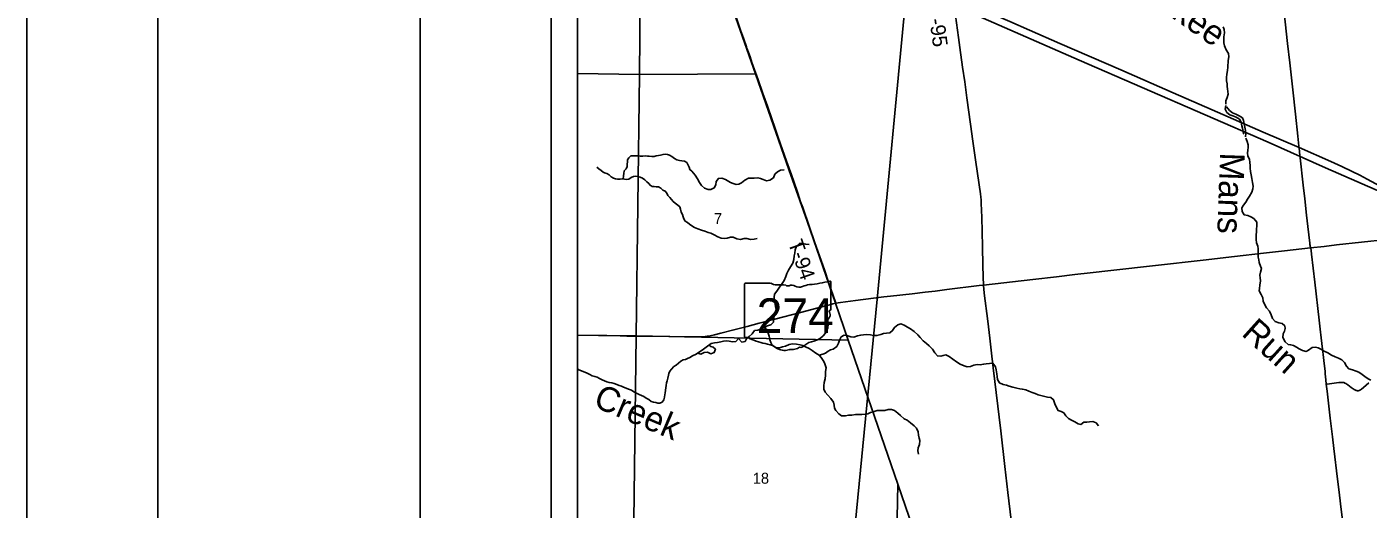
# Model space of a CAD drawing. Extents: x 0 to 34, y -5.4 to 22.
# Drawn here: x 0 to 5.12, y 16.49 to 18.33 of the extents above; entities that cross this region are included whole.
import ezdxf

# ---------------------------------------------------------------- set-up
doc = ezdxf.new("R2010")
doc.units = 0
for name, color, linetype in [('Default', 7, 'Continuous'), ('GM_X_Minor_River', 7, 'Continuous'), ('GM_X_Minor_River_Text', 7, 'Continuous'), ('GM_X_Rail_Line', 7, 'Continuous'), ('GM_X_Section', 7, 'Continuous'), ('GM_X_Section_Text', 7, 'Continuous'), ('GM_X_State_Location', 7, 'Continuous'), ('GM_X_State_Route', 7, 'Continuous'), ('GM_X_State_Shield', 7, 'Continuous'), ('GM_X_Township_Road', 7, 'Continuous'), ('GM_X_Township_Road_Text', 7, 'Continuous'), ('GM_X_US_Route', 7, 'Continuous'), ('SH_Border', 7, 'Continuous'), ('SH_Cut_Line', 7, 'Continuous'), ('SH_Data', 7, 'Continuous')]:
    doc.layers.add(name, color=color, linetype=linetype)

msp = doc.modelspace()

# ---------------------------------------------------------------- linework, layer by layer
at = {"layer": 'Default'}
for points in [[(2.1, 19.1639), (2.1, 18.1542), (2.3371, 18.1505), (2.3463, 19.1601)], [(2.1, 18.1542), (2.1, 17.1559), (2.3239, 17.1531), (2.3371, 18.1505)], [(2.1, 17.1559), (2.1, 16.1508), (2.3117, 16.1481), (2.3239, 17.1531)]]:
    msp.add_lwpolyline(points, close=True, dxfattribs=at)
at = {"layer": 'GM_X_Minor_River'}
for points in [[(4.5637, 18.333), (4.5673, 18.3223), (4.5686, 18.3094), (4.5661, 18.2951), (4.5659, 18.2814), (4.5665, 18.2719), (4.5682, 18.2609), (4.5747, 18.2445), (4.5836, 18.2306), (4.5849, 18.2181), (4.582, 18.2049), (4.5816, 18.1783), (4.5795, 18.1662), (4.5781, 18.1522), (4.576, 18.1393), (4.5758, 18.1264), (4.5783, 18.115), (4.5792, 18.1051), (4.5795, 18.0957), (4.5812, 18.0861), (4.5822, 18.0759), (4.5789, 18.0634), (4.5742, 18.0506), (4.5732, 18.0373)], [(4.5743, 18.032), (4.5714, 18.0184), (4.5772, 18.0065), (4.5892, 17.9965), (4.6009, 17.9936), (4.6133, 17.9877), (4.6264, 17.9799), (4.6326, 17.9684), (4.6351, 17.9555), (4.6368, 17.9456), (4.6392, 17.9322), (4.6428, 17.9227)], [(4.5768, 18.027), (4.588, 18.0136), (4.5995, 18.005), (4.6123, 17.9991), (4.6251, 17.9936), (4.6371, 17.985), (4.6407, 17.9755), (4.6431, 17.9625), (4.646, 17.9503), (4.6488, 17.9378), (4.6505, 17.9256), (4.6491, 17.9131)], [(4.6494, 17.9078), (4.6549, 17.8956), (4.6592, 17.8826), (4.6594, 17.8727), (4.6581, 17.8621), (4.6568, 17.8511), (4.6582, 17.8409), (4.6636, 17.8271), (4.6649, 17.8165), (4.6662, 17.8028), (4.6665, 17.7933), (4.6678, 17.7811), (4.6698, 17.7674), (4.6726, 17.7537), (4.675, 17.7385), (4.6774, 17.7244), (4.6773, 17.7142), (4.6733, 17.7017), (4.6643, 17.6871), (4.6569, 17.6747), (4.6503, 17.6642), (4.6407, 17.6518), (4.6345, 17.642), (4.6365, 17.6283), (4.6439, 17.6153), (4.6578, 17.6132), (4.6695, 17.608), (4.6807, 17.601), (4.6918, 17.5872), (4.6923, 17.572), (4.6907, 17.5621), (4.6901, 17.5527), (4.6895, 17.5367), (4.6889, 17.5219), (4.6902, 17.5086), (4.6953, 17.496), (4.697, 17.4861), (4.6968, 17.4759), (4.697, 17.4656), (4.6976, 17.4539), (4.699, 17.444), (4.701, 17.4329), (4.7065, 17.4199), (4.7094, 17.4104), (4.7058, 17.3968), (4.7029, 17.3847), (4.705, 17.3748), (4.706, 17.363), (4.7031, 17.3471), (4.7017, 17.3346), (4.7008, 17.3248), (4.7085, 17.3113), (4.7148, 17.2983), (4.7157, 17.2866), (4.7219, 17.2724), (4.7289, 17.2601), (4.7404, 17.2478), (4.747, 17.234), (4.7521, 17.2203), (4.7625, 17.2087), (4.7757, 17.2039), (4.7885, 17.2011), (4.7985, 17.1918), (4.7999, 17.1819), (4.7978, 17.1717), (4.7924, 17.1615), (4.791, 17.1471), (4.8006, 17.1314), (4.8114, 17.121), (4.8212, 17.1189), (4.8318, 17.1172), (4.8438, 17.1109), (4.8535, 17.1043), (4.8655, 17.098), (4.8798, 17.0944), (4.8894, 17.0991), (4.9024, 17.1088), (4.916, 17.1101), (4.9259, 17.108), (4.936, 17.1033), (4.9487, 17.0955), (4.963, 17.0884), (4.9772, 17.0798), (4.9911, 17.0735), (5.0035, 17.0684), (5.0159, 17.0625), (5.0267, 17.0516), (5.0337, 17.0379), (5.043, 17.0278), (5.0569, 17.0234), (5.0705, 17.0194), (5.081, 17.0147), (5.0933, 17.0057), (5.1034, 16.998), (5.1165, 16.9894), (5.1267, 16.9843)], [(2.2745, 17.7517), (2.2762, 17.7646), (2.2767, 17.7733), (2.2792, 17.7832), (2.2865, 17.791), (2.2897, 17.8004), (2.2906, 17.8088), (2.2907, 17.8175), (2.2916, 17.8254), (2.2963, 17.8329), (2.304, 17.8404), (2.3127, 17.841), (2.321, 17.8409), (2.3313, 17.8399), (2.34, 17.839), (2.3494, 17.8388), (2.3589, 17.8402), (2.3676, 17.8397), (2.3741, 17.8396), (2.3843, 17.8382), (2.3933, 17.8381), (2.401, 17.8406), (2.4093, 17.842), (2.4177, 17.8437), (2.4272, 17.8462), (2.4367, 17.8464), (2.4435, 17.8456), (2.4518, 17.8431), (2.46, 17.8384), (2.4709, 17.8299), (2.4799, 17.8248), (2.4893, 17.8231), (2.4987, 17.8211), (2.5086, 17.8198), (2.5176, 17.8147), (2.5231, 17.8055), (2.5264, 17.7974), (2.5289, 17.7883), (2.5367, 17.7821), (2.5427, 17.7748), (2.5497, 17.7668)], [(2.5467, 17.5665), (2.5373, 17.573), (2.5284, 17.58), (2.5201, 17.5866), (2.5111, 17.5917), (2.506, 17.5998), (2.5038, 17.6078), (2.5006, 17.6169), (2.4966, 17.6257), (2.493, 17.6364), (2.4908, 17.6455), (2.483, 17.6529), (2.4725, 17.6599), (2.4658, 17.6661), (2.4591, 17.6738), (2.4532, 17.6819), (2.4457, 17.6892), (2.4413, 17.6976), (2.4354, 17.7061), (2.4264, 17.7097), (2.4182, 17.7166), (2.4099, 17.7217), (2.4009, 17.7226), (2.3929, 17.7235), (2.3853, 17.724), (2.3775, 17.728), (2.3727, 17.7349), (2.3652, 17.7418), (2.3578, 17.7495), (2.3484, 17.755), (2.339, 17.7586), (2.3311, 17.7618), (2.3235, 17.763), (2.3144, 17.7617), (2.3056, 17.7573), (2.296, 17.7514), (2.2884, 17.7496), (2.2797, 17.7509), (2.2714, 17.7522), (2.2635, 17.7512), (2.254, 17.7513), (2.2453, 17.753), (2.2374, 17.7558), (2.2291, 17.7605), (2.2213, 17.7675), (2.2131, 17.7729), (2.204, 17.7754), (2.198, 17.7781), (2.1905, 17.7847), (2.1823, 17.7909), (2.1745, 17.7979)], [(2.5497, 17.7668), (2.5589, 17.753), (2.5659, 17.7389), (2.5737, 17.727), (2.5856, 17.7177), (2.5984, 17.7121), (2.6086, 17.7116), (2.622, 17.7182), (2.6278, 17.7295), (2.6299, 17.7423), (2.6384, 17.7543), (2.6517, 17.7556), (2.6649, 17.7501), (2.6844, 17.7391), (2.6949, 17.7348), (2.7054, 17.7312), (2.7157, 17.7325), (2.7267, 17.7376), (2.7394, 17.7473), (2.7531, 17.7554), (2.7648, 17.7548), (2.7751, 17.755), (2.7891, 17.7567), (2.7989, 17.7546), (2.8087, 17.7503), (2.8211, 17.7455), (2.8347, 17.7476), (2.8485, 17.7572), (2.8533, 17.77), (2.8633, 17.7793), (2.8755, 17.7856), (2.8884, 17.7865)], [(2.5467, 17.5665), (2.5592, 17.5621), (2.5735, 17.5569), (2.5867, 17.5537), (2.5995, 17.5485), (2.6093, 17.5457), (2.6221, 17.5386), (2.6356, 17.5316), (2.6483, 17.526), (2.6623, 17.525), (2.6718, 17.5268), (2.6844, 17.5296), (2.6946, 17.5302), (2.7089, 17.5243), (2.7228, 17.521), (2.7358, 17.5253), (2.746, 17.5255), (2.7603, 17.5215), (2.7739, 17.5231), (2.7861, 17.5256)], [(2.8139, 17.1842), (2.8242, 17.1916), (2.8375, 17.1963), (2.8483, 17.2064), (2.8488, 17.2159), (2.8509, 17.2291), (2.8595, 17.2442), (2.8581, 17.2537), (2.8564, 17.2647), (2.8551, 17.2746), (2.8526, 17.2883), (2.8506, 17.3013), (2.8519, 17.3123), (2.8604, 17.3246), (2.8716, 17.3389), (2.8782, 17.3494), (2.8895, 17.3652), (2.895, 17.3799), (2.8986, 17.3916), (2.9056, 17.4044), (2.9134, 17.4175), (2.9215, 17.4307), (2.9252, 17.445), (2.9277, 17.4586), (2.9297, 17.4685), (2.9311, 17.4821), (2.9366, 17.4957), (2.947, 17.5065), (2.9595, 17.5059), (2.9715, 17.5031), (2.9844, 17.5025)], [(2.5395, 17.0776), (2.5538, 17.0831), (2.5664, 17.0924), (2.5764, 17.099), (2.586, 17.1068), (2.5967, 17.1142), (2.6105, 17.1239), (2.6238, 17.1275), (2.634, 17.1284), (2.6469, 17.1309), (2.6571, 17.133), (2.6674, 17.1343), (2.6787, 17.133), (2.6919, 17.1308), (2.7048, 17.1321), (2.7141, 17.1438), (2.7275, 17.1299), (2.74, 17.1319), (2.7458, 17.1417), (2.7554, 17.1506), (2.7673, 17.1607), (2.7762, 17.1735), (2.7888, 17.1751), (2.801, 17.181), (2.8116, 17.1858), (2.8229, 17.178), (2.8315, 17.152), (2.8347, 17.139), (2.838, 17.1284), (2.8431, 17.1184), (2.857, 17.1098), (2.8709, 17.1084), (2.8831, 17.1113), (2.8934, 17.1145), (2.9075, 17.1203), (2.9208, 17.1228), (2.9366, 17.1217), (2.9502, 17.1192), (2.9604, 17.1168), (2.9702, 17.1121), (2.9841, 17.1057), (2.996, 17.0983), (3.0099, 17.0871), (3.023, 17.08), (3.0359, 17.084), (3.0466, 17.088), (3.0562, 17.095), (3.0657, 17.0998), (3.0763, 17.1026), (3.0898, 17.1127), (3.0964, 17.1251), (3.1, 17.1368), (3.1059, 17.1496), (3.1177, 17.1566), (3.1324, 17.1533), (3.1426, 17.1497), (3.1547, 17.1484), (3.1691, 17.1531), (3.1809, 17.1567), (3.1915, 17.1576), (3.2044, 17.1582), (3.2188, 17.1575), (3.2297, 17.1555), (3.2429, 17.1549), (3.2578, 17.1592), (3.2673, 17.1624), (3.2787, 17.1634), (3.2915, 17.165), (3.3023, 17.1736), (3.3097, 17.186), (3.3219, 17.196), (3.3337, 17.2), (3.3465, 17.1949), (3.36, 17.1867), (3.3705, 17.1804), (3.3843, 17.1699), (3.3985, 17.1571), (3.4074, 17.1467), (3.4193, 17.1348), (3.4324, 17.1239), (3.4425, 17.1154), (3.4544, 17.1034), (3.4633, 17.0888), (3.4733, 17.0773), (3.4865, 17.0759), (3.496, 17.0792), (3.5059, 17.0809), (3.5183, 17.0746), (3.5321, 17.0645), (3.546, 17.054), (3.5598, 17.0458), (3.5752, 17.0387), (3.5865, 17.0355), (3.6002, 17.0371), (3.612, 17.0423), (3.6253, 17.0439), (3.637, 17.043), (3.6495, 17.045), (3.659, 17.0468), (3.6855, 17.0494), (3.6955, 17.0359)], [(2.5596, 17.0874), (2.5716, 17.0843), (2.5838, 17.0898), (2.5971, 17.0915), (2.6098, 17.0855), (2.622, 17.0903), (2.6264, 17.1027), (2.6183, 17.1108), (2.6093, 17.1129), (2.6023, 17.1182)], [(2.4422, 16.9826), (2.4447, 16.9917), (2.4475, 17.0034), (2.4495, 17.0094), (2.4534, 17.0192), (2.4589, 17.0271), (2.4681, 17.0361), (2.4765, 17.042), (2.4858, 17.0498), (2.4946, 17.0565), (2.5038, 17.0616), (2.5121, 17.0638), (2.5205, 17.067), (2.5285, 17.0707), (2.5395, 17.0776)], [(3.0229, 17.0801), (3.0301, 17.0715), (3.0378, 17.0596), (3.0433, 17.0501), (3.0487, 17.0317), (3.047, 17.0181), (3.046, 17.0033), (3.045, 16.9897), (3.0421, 16.9757), (3.0397, 16.9628), (3.0398, 16.9506), (3.045, 16.9388), (3.0554, 16.9272), (3.0673, 16.9149), (3.0765, 16.9003), (3.0797, 16.8892), (3.0803, 16.8778), (3.0858, 16.8682), (3.097, 16.8559), (3.1071, 16.8489), (3.1218, 16.8482), (3.1351, 16.851), (3.1469, 16.8516), (3.1613, 16.8529), (3.1741, 16.8534), (3.1847, 16.8536), (3.198, 16.8549), (3.2075, 16.8566), (3.2185, 16.8606), (3.2288, 16.8639), (3.2437, 16.8693), (3.2592, 16.8687), (3.2728, 16.8688), (3.2853, 16.8724), (3.2986, 16.8726), (3.3095, 16.869), (3.3222, 16.8585), (3.333, 16.8503), (3.3472, 16.8376), (3.3577, 16.8313), (3.3708, 16.822), (3.3842, 16.8104), (3.3939, 16.8018), (3.4001, 16.7873), (3.4014, 16.7751), (3.4039, 16.7637), (3.4064, 16.7542), (3.4054, 16.7394), (3.3999, 16.7262), (3.3993, 16.7148), (3.4014, 16.7022)], [(2.1, 17.0282), (2.1054, 17.0245), (2.116, 17.0202), (2.1242, 17.0162), (2.1348, 17.0122), (2.1472, 17.006), (2.1569, 17.0008), (2.1663, 16.9984), (2.175, 16.9956), (2.1844, 16.9913), (2.1942, 16.9862), (2.2039, 16.9814), (2.2126, 16.9779), (2.2217, 16.9758), (2.2311, 16.9745), (2.2402, 16.9721), (2.2511, 16.9681), (2.2597, 16.9641), (2.2684, 16.961), (2.2763, 16.9582), (2.2861, 16.9542), (2.2951, 16.9499), (2.3064, 16.9459), (2.3154, 16.9404), (2.3282, 16.9341), (2.3364, 16.9302), (2.3443, 16.9258), (2.353, 16.9219), (2.3623, 16.916), (2.3721, 16.9102), (2.3822, 16.9028), (2.3908, 16.9), (2.3988, 16.8987), (2.4071, 16.8967), (2.415, 16.8965), (2.4234, 16.9009), (2.4297, 16.9099), (2.4321, 16.9201), (2.4341, 16.9292), (2.435, 16.9353), (2.4367, 16.9466), (2.4376, 16.9557), (2.4389, 16.9641), (2.4402, 16.9743), (2.4422, 16.9826)], [(3.6955, 17.0359), (3.698, 17.0237), (3.7, 17.0089), (3.701, 16.9986), (3.7027, 16.9868), (3.7108, 16.9741), (3.7243, 16.9686), (3.7364, 16.965), (3.7466, 16.9621), (3.7616, 16.9573), (3.7763, 16.954), (3.7873, 16.952), (3.7975, 16.9499), (3.8103, 16.9474), (3.8227, 16.9422), (3.8355, 16.9375), (3.846, 16.9335), (3.858, 16.9283), (3.8682, 16.9259), (3.8833, 16.9222), (3.8935, 16.9202), (3.9063, 16.918), (3.9168, 16.9099), (3.9218, 16.8939), (3.9265, 16.8824), (3.9335, 16.869), (3.9456, 16.8646), (3.9553, 16.8599), (3.9631, 16.848), (3.9731, 16.8387), (3.9848, 16.8324), (3.9971, 16.8254), (4.0099, 16.8176), (4.0212, 16.8151), (4.0316, 16.8237), (4.044, 16.8238), (4.0535, 16.8252), (4.0668, 16.8272), (4.0785, 16.8221), (4.0885, 16.8102)]]:
    msp.add_lwpolyline(points, dxfattribs=at)
at = {"layer": 'GM_X_Rail_Line'}
msp.add_lwpolyline([(2.1, 20.2033), (2.1, 14.1), (2.9527, 14.1), (2.9641, 14.2324), (3.0059, 14.7462), (3.0382, 15.1455), (3.0967, 15.7517), (3.13, 16.1326), (3.2432, 17.2942), (3.3599, 18.5136), (3.3607, 18.5226), (3.3669, 18.5872), (3.3865, 18.7781), (3.4297, 19.2264), (3.4301, 19.2311), (3.4303, 19.2337), (3.46, 19.8188), (3.4778, 20.1697), (3.2417, 20.1756), (2.1537, 20.2026)], close=True, dxfattribs=at)
for points in [[(8.9, 15.5944), (8.9, 19.2127), (8.5201, 19.1691), (7.2315, 19.0156), (6.9054, 18.9823), (6.6792, 18.9603), (6.4496, 18.9373), (6.0045, 18.8908), (5.7334, 18.8597), (5.7313, 18.8595), (5.378, 18.814), (5.096, 18.7806), (5.0255, 18.7742), (4.7505, 18.7432), (3.5131, 18.6037), (3.3669, 18.5872), (3.3607, 18.5226), (3.3599, 18.5136), (3.2432, 17.2942), (3.13, 16.1326)], [(2.1, 19.046), (2.5086, 18.8639), (2.5191, 18.86), (3.2213, 18.5539), (4.0144, 18.2052), (4.7357, 17.8926), (4.9545, 17.7944), (5.8917, 17.3857), (5.944, 17.3605), (5.9893, 17.3246), (6.0173, 17.2941), (6.0405, 17.2593), (6.0551, 17.2305), (6.1298, 17.0307)]]:
    msp.add_lwpolyline(points, dxfattribs=at)
at = {"layer": 'GM_X_Section'}
for points in [[(2.4277, 19.1584), (2.7791, 18.153), (2.3371, 18.1505), (2.3463, 19.1601)], [(2.3371, 18.1505), (2.7791, 18.153), (2.9068, 17.789), (2.9768, 17.5914), (3.0847, 17.2789), (3.1329, 17.1374), (2.3239, 17.1531)], [(2.3239, 17.1531), (3.1329, 17.1374), (3.323, 16.5877), (3.3134, 16.1326), (2.3117, 16.1481)], [(3.3134, 16.1326), (3.323, 16.5877), (3.4807, 16.1279)]]:
    msp.add_lwpolyline(points, close=True, dxfattribs=at)
at = {"layer": 'GM_X_State_Route'}
for points in [[(3.2697, 17.3019), (3.2947, 17.3049), (3.3774, 17.3144), (3.4262, 17.3201), (3.4644, 17.3247), (3.51, 17.3304), (3.6322, 17.3452), (3.6491, 17.3472), (3.8378, 17.369), (3.9279, 17.3794), (3.9971, 17.3871), (4.0557, 17.394), (4.1353, 17.4032), (4.3052, 17.4223), (4.4873, 17.4428), (4.6071, 17.4564), (4.7171, 17.4686), (4.7969, 17.4777), (4.8972, 17.489), (4.9487, 17.4949), (4.9955, 17.5005), (5.1865, 17.5218)], [(2.1, 17.1562), (2.1808, 17.1546), (2.2636, 17.1533), (2.2887, 17.1529), (2.3755, 17.1523), (2.453, 17.1513), (2.5081, 17.1503), (2.5645, 17.1498), (2.583, 17.1505), (2.5878, 17.151), (2.5924, 17.1515), (2.597, 17.1521), (2.6063, 17.1535), (2.6232, 17.1572), (2.6473, 17.1633), (2.6973, 17.1761), (2.7477, 17.1894), (2.7938, 17.2019), (2.8535, 17.2176), (2.9513, 17.2431), (2.9939, 17.2545), (3.047, 17.2685), (3.0633, 17.2726), (3.0747, 17.2754), (3.086, 17.2781), (3.1036, 17.2809), (3.1614, 17.2888), (3.2697, 17.3019)]]:
    msp.add_lwpolyline(points, dxfattribs=at)
at = {"layer": 'GM_X_State_Shield'}
for p, q in [((2.7376, 17.3509), (2.7376, 17.1508)), ((2.8374, 17.3544), (2.7409, 17.3544)), ((3.0672, 17.2546), (3.0672, 17.3593)), ((3.0672, 17.2546), (3.0672, 17.2546))]:
    msp.add_line(p, q, dxfattribs=at)
for centre, major_axis, start_param, end_param in [((2.7414, 17.3513), (0.00382, 0), 1.712693, 3.28349), ((2.8604, 17.3776), (0.037, 0), 4.042523, 4.731795), ((2.8727, 17.242), (0.133, 0), 1.404758, 1.657858), ((2.9029, 17.3524), (0.0107, 0), 3.836095, 5.185415), ((2.9185, 17.3292), (0.0222, 0), 0.950623, 2.079405), ((2.9944, 17.2932), (0.0703, 0), 1.699011, 2.107814), ((2.9498, 17.6272), (0.3495, 0), 4.814394, 5.042369), ((3.0636, 17.3597), (0.00367, 0), 6.141152, 7.989035), ((2.9472, 17.361), (0.0267, 0), 4.081561, 5.145723), ((3.0664, 17.2469), (0.00568, 0), 1.883978, 3.671073), ((3.0302, 17.2337), (0.0341, 0), 5.934695, 6.695948), ((3.0633, 17.2542), (0.00393, 0), 5.05454, 6.418171), ((2.9694, 17.1975), (0.0874, 0), 5.101752, 6.440018), ((3.0804, 17.2108), (0.0248, 0), 2.387724, 3.262537), ((2.7414, 17.1503), (0.00385, 0), 3.00124, 4.508301), ((2.742, 17.1708), (0.0294, 0), 4.665946, 4.897461), ((2.748, 17.1392), (0.0106, 0), 0.519207, 1.627899), ((2.8819, 17.319), (0.2524, 0), 4.195997, 4.488961), ((2.8066, 17.0609), (0.079, 0), 0.823519, 1.323587), ((2.892, 17.1382), (0.0501, 0), 4.026481, 4.996735), ((2.921, 17.0691), (0.0412, 0), 1.495662, 1.94098), ((2.9246, 17.1233), (0.0267, 0), 4.691044, 5.507374), ((2.9488, 17.1039), (0.00752, 0), 1.147584, 2.315152), ((2.9456, 17.1314), (0.0282, 0), 4.937069, 5.64225), ((3.0063, 17.0946), (0.0479, 0), 1.647645, 2.488434)]:
    msp.add_ellipse(centre, major_axis=major_axis, ratio=0.8, start_param=start_param, end_param=end_param, dxfattribs=at)
at = {"layer": 'GM_X_Township_Road'}
for points in [[(2.745, 18.2567), (2.7333, 18.289), (2.7222, 18.3204), (2.7146, 18.3424), (2.7027, 18.3775), (2.6904, 18.4139), (2.6774, 18.4512), (2.6689, 18.4762), (2.6568, 18.5108), (2.6502, 18.5295), (2.6417, 18.5536), (2.64, 18.5582)], [(3.6522, 17.3176), (3.6491, 17.3455), (3.6491, 17.3472), (3.6489, 17.3535), (3.6483, 17.3722), (3.6454, 17.4871), (3.6438, 17.5586), (3.6414, 17.64), (3.6409, 17.6528), (3.6398, 17.6729), (3.6389, 17.6831), (3.6374, 17.6958), (3.6203, 17.8158), (3.6086, 17.8963), (3.5997, 17.961), (3.5862, 18.062), (3.5776, 18.1223), (3.5694, 18.1795), (3.5593, 18.2533), (3.554, 18.2921), (3.5421, 18.3758), (3.5356, 18.4194), (3.5326, 18.4425), (3.532, 18.4478)], [(5.0306, 16.3581), (5.0117, 16.5123), (5.006, 16.5566), (5.0001, 16.6066), (4.9858, 16.7244), (4.9803, 16.7688), (4.9719, 16.8392), (4.9652, 16.8965), (4.9596, 16.9428), (4.9567, 16.9694), (4.9549, 16.986), (4.953, 17.0083), (4.9521, 17.0179), (4.951, 17.0292), (4.9489, 17.0482), (4.9448, 17.0829), (4.9425, 17.1024), (4.9376, 17.1463), (4.934, 17.1796), (4.9297, 17.2141), (4.913, 17.3585), (4.9009, 17.4647), (4.8995, 17.4787), (4.8993, 17.4806), (4.8989, 17.4829), (4.8985, 17.4847), (4.8981, 17.4861), (4.8972, 17.489), (4.8964, 17.4918), (4.8957, 17.495), (4.895, 17.4982), (4.8943, 17.5019), (4.8936, 17.5073), (4.8899, 17.5388), (4.8862, 17.5715), (4.8816, 17.6137), (4.8745, 17.6762), (4.869, 17.7281), (4.8574, 17.8325), (4.8551, 17.8551), (4.8532, 17.8719), (4.8526, 17.8772), (4.8482, 17.9159), (4.839, 17.9999), (4.8287, 18.0919), (4.8175, 18.1951), (4.8094, 18.2692), (4.796, 18.3877)], [(3.086, 17.2781), (3.0762, 17.308), (3.0584, 17.3589), (3.0423, 17.4056), (3.0254, 17.455), (3.0051, 17.5127), (2.9854, 17.5688), (2.9601, 17.6431), (2.9518, 17.6656), (2.9407, 17.698), (2.9255, 17.742), (2.9165, 17.768), (2.9028, 17.8066), (2.8907, 17.8421), (2.8659, 17.911), (2.8535, 17.9484), (2.8429, 17.9784), (2.8249, 18.0301), (2.8076, 18.0789), (2.7897, 18.13), (2.7662, 18.1972), (2.7587, 18.2184), (2.7471, 18.251), (2.745, 18.2567)], [(3.7969, 16.0976), (3.7889, 16.1601), (3.7822, 16.2212), (3.7757, 16.2774), (3.7677, 16.3453), (3.7426, 16.5563), (3.7308, 16.655), (3.7149, 16.7914), (3.6867, 17.0315), (3.679, 17.0988), (3.6735, 17.1451), (3.6652, 17.2098), (3.6524, 17.3166), (3.6522, 17.3176)], [(4.9567, 16.9694), (4.9599, 16.9698), (5.0044, 16.9751), (5.0126, 16.976), (5.0175, 16.9761), (5.021, 16.9758), (5.0238, 16.9751), (5.0264, 16.9742), (5.0282, 16.9733), (5.0315, 16.9714), (5.0349, 16.9693), (5.039, 16.9666), (5.0521, 16.957), (5.0629, 16.9494), (5.0657, 16.9474), (5.0683, 16.9461), (5.0708, 16.9451), (5.0732, 16.9445), (5.0759, 16.9442), (5.0787, 16.9443), (5.0817, 16.945), (5.0842, 16.9461), (5.0868, 16.9476), (5.0906, 16.9502), (5.0982, 16.9561), (5.1196, 16.9749)]]:
    msp.add_lwpolyline(points, dxfattribs=at)
at = {"layer": 'GM_X_US_Route'}
msp.add_lwpolyline([(3.532, 18.4478), (3.5914, 18.422), (3.7499, 18.3528), (3.8252, 18.32), (3.941, 18.2697), (4.1735, 18.1684), (4.3734, 18.0813), (4.5219, 18.0164), (4.7167, 17.9313), (4.8532, 17.8719), (4.9739, 17.8194), (5.0157, 17.8001), (5.0561, 17.7807), (5.085, 17.7662), (5.1134, 17.7513), (5.1461, 17.7339), (5.1724, 17.7191), (5.2235, 17.6893), (5.2562, 17.6694), (5.2871, 17.6497), (5.3178, 17.6291), (5.3505, 17.6064), (5.3906, 17.5783), (5.4298, 17.5482)], dxfattribs=at)
at = {"layer": 'SH_Border'}
for points in [[(0.5, 21.5), (1.5, 21.5), (1.5, 0.5), (0.5, 0.5)], [(1.5, 21.5), (33.5, 21.5), (33.5, 0.5), (1.5, 0.5)]]:
    msp.add_lwpolyline(points, close=True, dxfattribs=at)
at = {"layer": 'SH_Cut_Line'}
msp.add_lwpolyline([(0, 0), (34, 0), (34, 22), (0, 22)], close=True, dxfattribs=at)
at = {"layer": 'SH_Data'}
for p, q in [((2, 21), (2, 14)), ((2.1, 20.9), (2.1, 14.1))]:
    msp.add_line(p, q, dxfattribs=at)

# ---------------------------------------------------------------- texts
at = {"layer": 'GM_X_Minor_River_Text'}
for s, height, rotation, p in [('Cherokee', 0.09471, 325.0277, (4.0804, 18.5678)), ('Mans', 0.09474, 268.0452, (4.5517, 17.8541)), ('Run', 0.09475, 318.022, (4.6297, 17.1579)), ('Creek', 0.09474, 337.0122, (2.1564, 16.8857))]:
    msp.add_text(s, height=height, rotation=rotation, dxfattribs=at).set_placement(p)
at = {"layer": 'GM_X_Section_Text'}
for s, height, p in [('7', 0.0419, (2.621, 17.5799)), ('18', 0.04186, (2.769, 16.5894))]:
    msp.add_text(s, height=height, rotation=0, dxfattribs=at).set_placement(p)
at = {"layer": 'GM_X_State_Location'}
msp.add_text('274', height=0.000189, rotation=0, dxfattribs=at).set_placement((2.8319, 17.2238))
for s in ['s', 'r']:
    msp.add_text(s, height=0.000189, dxfattribs=at).set_placement((2.8987, 17.2375))
at = {"layer": 'GM_X_State_Shield'}
msp.add_text('274', height=0.13184, dxfattribs=at).set_placement((2.7842, 17.1649))
at = {"layer": 'GM_X_Township_Road_Text'}
for s, rotation, p in [('T-95', 277.7781, (3.4365, 18.4077)), ('T-94', 289.4403, (2.903, 17.509))]:
    msp.add_text(s, height=0.05682, rotation=rotation, dxfattribs=at).set_placement(p)

doc.saveas('drawing.dxf')
